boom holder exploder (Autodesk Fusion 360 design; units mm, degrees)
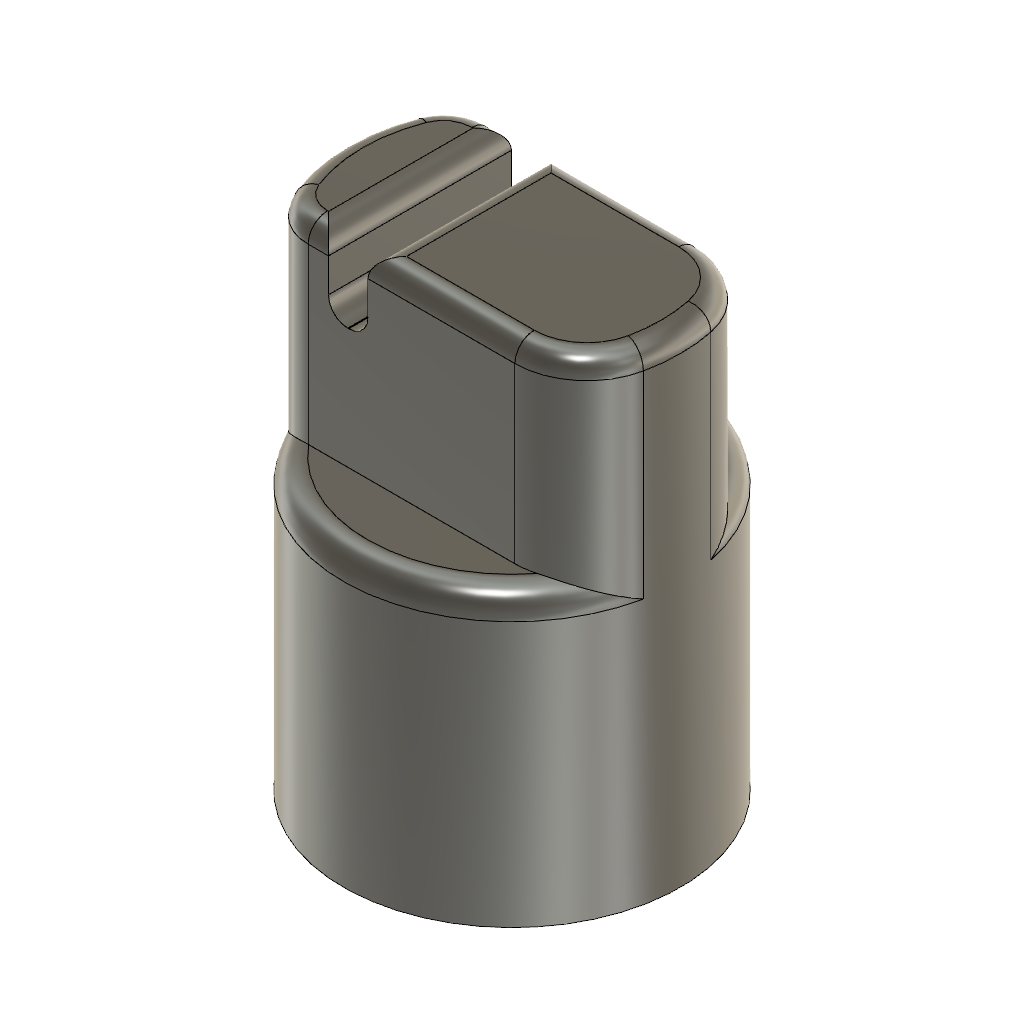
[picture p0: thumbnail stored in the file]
sketch "Sketch1" plane through (0, 0, 0) normal (0, 0, 1) x axis (1, 0, 0)
  circle C1 centre (0, 0) radius 31
  circle C2 centre (0, 0) radius 35
  point P1 (0, 0)
  point P2 (0, 0)
  point P3 (0, 0)
  coincident P1 P2
  coincident P1 P3
  dimension "d1" diameter C1 = 62
  dimension "d2" diameter C2 = 70
extrude "Extrude1" new body sketch "Sketch1" along normal blind 50
sketch "Sketch2" plane through (0, 0, 50) normal (0, 0, 1) x axis (-1, 0, 0)
  circle C1 centre (0, 0) radius 31
  circle C2 centre (0, 0) radius 35
  circle C3 centre (0, 0) radius 35
  concentric C1 C3
extrude "Extrude2" add sketch "Sketch2" along normal blind 5
sketch "Sketch3" plane through (0, 0, 55) normal (0, 0, 1) x axis (-1, 0, 0)
  circle C1 centre (0, 0) radius 35
  circle C2 centre (0, 0) radius 8
  point P1 (0, 0)
  point P3 (0, 0)
  coincident P1 P3
  dimension "d7" diameter C2 = 16
extrude "Extrude3" cut sketch "Sketch3" profile of C2 against normal blind 20
sketch "Sketch4" plane through (0, 0, 55) normal (0, 0, 1) x axis (-1, 0, 0)
  line L1 (0, -19) -> (0, 0)
  line L2 (29.3939, -19) -> (0, -19)
  line L3 (-29.3939, -19) -> (29.3939, -19)
  line L4 (-29.3939, 19) -> (-29.3939, -19)
  line L5 (29.3939, 19) -> (-29.3939, 19)
  line L6 (29.3939, -19) -> (29.3939, 19)
  circle C1 centre (0, 0) radius 8
  circle C2 centre (0, 0) radius 35
  point P2 (0, 0)
  point P3 (0, 0)
  point P5 (29.3939, -19)
  point P7 (-29.3939, 19)
  point P4 (0, -19)
  point P8 (29.3939, 19)
  coincident P2 P3
  vertical L1
  coincident C2 P5
  perpendicular L1 L2
  horizontal L3
  vertical L4
  horizontal L5
  vertical L6
  coincident C2 P7
  dimension "d10" distance P3 P4 = 19
  dimension "d11" distance P5 P8 = 38
extrude "Extrude4" add sketch "Sketch4" along normal blind 30
sketch "Sketch5" plane through (0, 0, 85) normal (0, 0, 1) x axis (-1, 0, 0)
  line L1 (-29.3939, 19) -> (29.3939, 19)
  line L2 (29.3939, -19) -> (-29.3939, -19)
  circle C1 centre (0, 0) radius 8
  arc A1 centre (0, 0) radius 35 clockwise from (29.3939, 19) to (29.3939, -19)
  arc A2 centre (0, 0) radius 35 clockwise from (-29.3939, -19) to (-29.3939, 19)
  circle C2 centre (0, 0) radius 8
  point P1 (0, 0)
  point P7 (0, 0)
  coincident P1 P7
extrude "Extrude5" add sketch "Sketch5" along normal blind 10
sketch "Sketch6" plane through (0, 0, 95) normal (0, 0, 1) x axis (-1, 0, 0)
  line L1 (29.3939, -19) -> (-29.3939, -19)
  line L2 (-29.3939, 19) -> (29.3939, 19)
  line L3 (35, 0) -> (0, 0)
  line L4 (15, 0) -> (35, 0)
  line L5 (19.1, 0) -> (15, 0)
  line L6 (10.9, 0) -> (19.1, 0)
  line L7 (10.9, -19) -> (10.9, 0)
  line L8 (19.1, -19) -> (10.9, -19)
  line L9 (19.1, 0) -> (19.1, -19)
  line L10 (10.9, 0) -> (19.1, 0)
  line L11 (10.9, 19) -> (10.9, 0)
  line L12 (19.1, 19) -> (10.9, 19)
  line L13 (19.1, 0) -> (19.1, 19)
  arc A1 centre (0, 0) radius 35 clockwise from (29.3939, 19) to (29.3939, -19)
  arc A2 centre (0, 0) radius 35 clockwise from (-29.3939, -19) to (-29.3939, 19)
  point P1 (0, 0)
  point P7 (0, 0)
  point P8 (35, 0)
  point P9 (15, 0)
  point P10 (19.1, 0)
  point P11 (10.9, 0)
  coincident P1 P7
  midpoint A1 P8
  parallel L3 L4
  parallel L4 L5
  horizontal L6
  vertical L7
  horizontal L8
  vertical L9
  horizontal L10
  vertical L11
  horizontal L12
  vertical L13
  dimension "d16" distance P8 P9 = 20
  dimension "d17" distance P9 P10 = 4.1
  dimension "d18" distance P10 P11 = 8.2
  dimension "d33" distance L11 L13 = 8.2
extrude "Extrude6" cut sketch "Sketch6" profile of L1 L2 L3 L4 L5 L6 L7 L8 L9 L10 L11 L12 L13 against normal blind 15
fillet "Fillet1" radius 4
fillet "Fillet2" radius 4
fillet "Fillet3" radius 12
fillet "Fillet4" radius 5
extrude "Extrude7" add of existing geometry blind 5
fillet "Fillet5" radius 5
fillet "Fillet6" radius 15
fillet "Fillet7" radius 10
